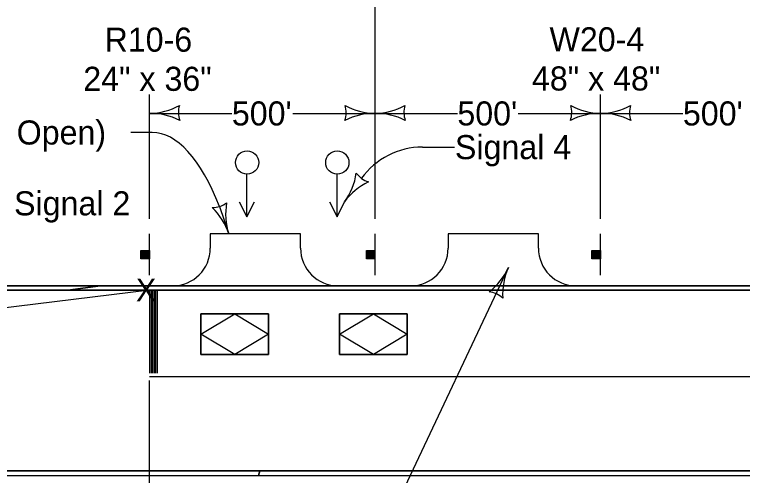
# Model space of a CAD drawing. Extents: x -2134934 to -2122394, y -2139046 to -2137036.
# Drawn here: x -2132604.2 to -2132120.1, y -2137668.2 to -2137362 of the extents above; entities that cross this region are included whole.
import ezdxf

# ---------------------------------------------------------------- set-up
doc = ezdxf.new("R2010")
doc.units = 0
for name, color, linetype in [('Barrier', 7, 'Continuous'), ('BridgeSuperStructureExisting', 7, 'Continuous'), ('DsnShtPlotIdentification', 7, 'Continuous'), ('DsnShtPlotShape', 7, 'Continuous'), ('dsnTextFinalPlan', 7, 'Continuous')]:
    doc.layers.add(name, color=color, linetype=linetype)

msp = doc.modelspace()

# ---------------------------------------------------------------- linework, layer by layer
at = {"layer": 'BridgeSuperStructureExisting'}
for p, q in [((-2132364.45, -2137497.66), (-2132364.45, -2137346.75)), ((-2132514.45, -2137497.66), (-2132514.45, -2137415.16)), ((-2132214.45, -2137497.66), (-2132214.45, -2137415.16)), ((-2132514.45, -2137427.66), (-2132459.7, -2137427.66)), ((-2132419.2, -2137427.66), (-2132364.45, -2137427.66)), ((-2132364.45, -2137427.66), (-2132309.7, -2137427.66)), ((-2132269.2, -2137427.66), (-2132214.45, -2137427.66)), ((-2132214.45, -2137427.66), (-2132159.7, -2137427.66)), ((-2132512.66, -2137440.32), (-2132526.88, -2137440.32)), ((-2132332.96, -2137450.05), (-2132311.59, -2137450.05)), ((-2132449.92, -2137468.02), (-2132449.92, -2137495.97)), ((-2132389.92, -2137468.02), (-2132389.92, -2137495.97)), ((-2132467.94, -2137489.45), (-2132461.8, -2137507.67)), ((-2132514.45, -2137535.16), (-2132514.45, -2137507.66)), ((-2132364.45, -2137535.16), (-2132364.45, -2137507.66)), ((-2132214.45, -2137535.16), (-2132214.45, -2137507.66)), ((-2132519.77, -2137524.3), (-2132519.77, -2137518.71)), ((-2132519.45, -2137518.71), (-2132519.45, -2137524.3)), ((-2132519.23, -2137524.3), (-2132519.23, -2137518.71)), ((-2132518.91, -2137518.71), (-2132518.91, -2137524.3)), ((-2132518.68, -2137524.3), (-2132518.7, -2137518.71)), ((-2132518.27, -2137518.71), (-2132518.25, -2137524.3)), ((-2132518.05, -2137524.3), (-2132518.05, -2137518.71)), ((-2132517.62, -2137518.71), (-2132517.62, -2137524.3)), ((-2132517.24, -2137524.3), (-2132517.24, -2137518.71)), ((-2132516.92, -2137518.71), (-2132516.9, -2137524.3)), ((-2132516.7, -2137524.3), (-2132516.7, -2137518.71)), ((-2132516.43, -2137518.71), (-2132516.43, -2137524.3)), ((-2132516.1, -2137524.3), (-2132516.1, -2137518.71)), ((-2132515.89, -2137518.71), (-2132515.89, -2137524.3)), ((-2132515.67, -2137524.3), (-2132515.67, -2137518.71)), ((-2132515.4, -2137518.71), (-2132515.4, -2137524.3)), ((-2132515.14, -2137524.3), (-2132515.14, -2137518.71)), ((-2132514.86, -2137518.71), (-2132514.86, -2137524.3)), ((-2132369.77, -2137524.3), (-2132369.77, -2137518.71)), ((-2132369.45, -2137518.71), (-2132369.45, -2137524.3)), ((-2132369.23, -2137524.3), (-2132369.23, -2137518.71)), ((-2132368.91, -2137518.71), (-2132368.91, -2137524.3)), ((-2132368.68, -2137524.3), (-2132368.7, -2137518.71)), ((-2132368.27, -2137518.71), (-2132368.25, -2137524.3)), ((-2132368.05, -2137524.3), (-2132368.05, -2137518.71)), ((-2132367.62, -2137518.71), (-2132367.62, -2137524.3)), ((-2132367.24, -2137524.3), (-2132367.24, -2137518.71)), ((-2132366.92, -2137518.71), (-2132366.9, -2137524.3)), ((-2132366.7, -2137524.3), (-2132366.7, -2137518.71)), ((-2132366.43, -2137518.71), (-2132366.43, -2137524.3)), ((-2132366.1, -2137524.3), (-2132366.1, -2137518.71)), ((-2132365.89, -2137518.71), (-2132365.89, -2137524.3)), ((-2132365.67, -2137524.3), (-2132365.67, -2137518.71)), ((-2132365.4, -2137518.71), (-2132365.4, -2137524.3)), ((-2132365.14, -2137524.3), (-2132365.14, -2137518.71)), ((-2132364.86, -2137518.71), (-2132364.86, -2137524.3)), ((-2132219.77, -2137524.3), (-2132219.77, -2137518.71)), ((-2132219.45, -2137518.71), (-2132219.45, -2137524.3)), ((-2132219.23, -2137524.3), (-2132219.23, -2137518.71)), ((-2132218.91, -2137518.71), (-2132218.91, -2137524.3)), ((-2132218.69, -2137524.3), (-2132218.7, -2137518.71)), ((-2132218.27, -2137518.71), (-2132218.25, -2137524.3)), ((-2132218.05, -2137524.3), (-2132218.05, -2137518.71)), ((-2132217.62, -2137518.71), (-2132217.62, -2137524.3)), ((-2132217.24, -2137524.3), (-2132217.24, -2137518.71)), ((-2132216.92, -2137518.71), (-2132216.9, -2137524.3)), ((-2132216.7, -2137524.3), (-2132216.7, -2137518.71)), ((-2132216.43, -2137518.71), (-2132216.43, -2137524.3)), ((-2132216.1, -2137524.3), (-2132216.1, -2137518.71)), ((-2132215.89, -2137518.71), (-2132215.89, -2137524.3)), ((-2132215.67, -2137524.3), (-2132215.67, -2137518.71)), ((-2132215.4, -2137518.71), (-2132215.4, -2137524.3)), ((-2132215.14, -2137524.3), (-2132215.14, -2137518.71)), ((-2132214.86, -2137518.71), (-2132214.86, -2137524.3)), ((-2132414.88, -2137824.64), (-2132275.76, -2137530.07)), ((-2132499.02, -2137542.16), (-2132389.02, -2137542.16)), ((-2132340.81, -2137542.16), (-2132230.81, -2137542.16)), ((-2131861.99, -2137545.16), (-2133174.44, -2137545.16)), ((-2132514.45, -2137545.16), (-2133004.39, -2137605.15)), ((-2132514.45, -2137545.16), (-2132514.45, -2137600.16)), ((-2132513.45, -2137545.16), (-2132513.45, -2137600.16)), ((-2132512.45, -2137545.16), (-2132512.45, -2137600.16)), ((-2132511.45, -2137545.16), (-2132511.45, -2137600.16)), ((-2132510.45, -2137545.16), (-2132510.45, -2137600.16)), ((-2132509.45, -2137545.16), (-2132509.45, -2137600.16)), ((-2132480.28, -2137587.78), (-2132480.28, -2137560.78)), ((-2132480.28, -2137560.78), (-2132435.28, -2137560.78)), ((-2132480.28, -2137587.78), (-2132480.28, -2137560.78)), ((-2132480.28, -2137560.78), (-2132435.28, -2137560.78)), ((-2132435.28, -2137560.78), (-2132480.28, -2137560.78)), ((-2132480.28, -2137560.78), (-2132480.28, -2137587.78)), ((-2132435.28, -2137587.78), (-2132435.28, -2137560.78)), ((-2132435.28, -2137560.78), (-2132435.28, -2137587.78)), ((-2132435.28, -2137587.78), (-2132435.28, -2137560.78)), ((-2132388.09, -2137587.86), (-2132388.09, -2137560.86)), ((-2132388.09, -2137560.86), (-2132343.09, -2137560.86)), ((-2132388.09, -2137587.86), (-2132388.09, -2137560.86)), ((-2132388.09, -2137560.86), (-2132343.09, -2137560.86)), ((-2132343.09, -2137560.86), (-2132388.09, -2137560.86)), ((-2132388.09, -2137560.86), (-2132388.09, -2137587.86)), ((-2132343.09, -2137587.86), (-2132343.09, -2137560.86)), ((-2132343.09, -2137560.86), (-2132343.09, -2137587.86)), ((-2132343.09, -2137587.86), (-2132343.09, -2137560.86)), ((-2132480.28, -2137587.78), (-2132435.28, -2137587.78)), ((-2132435.28, -2137587.78), (-2132480.28, -2137587.78)), ((-2132480.28, -2137587.78), (-2132435.28, -2137587.78)), ((-2132388.09, -2137587.86), (-2132343.09, -2137587.86)), ((-2132343.09, -2137587.86), (-2132388.09, -2137587.86)), ((-2132388.09, -2137587.86), (-2132343.09, -2137587.86)), ((-2132514.45, -2137842.77), (-2132514.45, -2137605.16)), ((-2133364.44, -2137665.16), (-2131861.99, -2137665.16))]:
    msp.add_line(p, q, dxfattribs=at)
for points in [[(-2132454.74, -2137486.34), (-2132449.74, -2137496.34), (-2132444.74, -2137486.34)], [(-2132394.74, -2137486.34), (-2132389.74, -2137496.34), (-2132384.74, -2137486.34)], [(-2132414.02, -2137517.16), (-2132414.02, -2137507.67), (-2132474.02, -2137507.67), (-2132474.02, -2137517.16)], [(-2132255.81, -2137517.16), (-2132255.81, -2137507.67), (-2132315.81, -2137507.67), (-2132315.81, -2137517.16)]]:
    msp.add_lwpolyline(points, dxfattribs=at)
for points in [[(-2132514.54, -2137518.71), (-2132514.54, -2137524.34), (-2132520.17, -2137524.34), (-2132520.17, -2137518.71)], [(-2132364.54, -2137518.71), (-2132364.54, -2137524.34), (-2132370.17, -2137524.34), (-2132370.17, -2137518.71)], [(-2132214.54, -2137518.71), (-2132214.54, -2137524.34), (-2132220.17, -2137524.34), (-2132220.17, -2137518.71)]]:
    msp.add_lwpolyline(points, close=True, dxfattribs=at)
for centre in [(-2132449.56, -2137460.29), (-2132389.56, -2137460.29)]:
    msp.add_circle(centre, 7.74, dxfattribs=at)
for centre, radius, start, end in [((-2132515.2, -2137385.17), 42.5, 271.0176, 299.0725), ((-2132478.83, -2137427.04), 16.42, 163.2666, 198.7334), ((-2132400.06, -2137427.04), 16.42, 341.2666, 16.7334), ((-2132363.69, -2137385.17), 42.5, 240.9275, 268.9824), ((-2132365.2, -2137385.17), 42.5, 271.0176, 299.0725), ((-2132328.83, -2137427.04), 16.42, 163.2666, 198.7334), ((-2132250.06, -2137427.04), 16.42, 341.2666, 16.7334), ((-2132213.69, -2137385.17), 42.5, 240.9275, 268.9824), ((-2132215.2, -2137385.17), 42.5, 271.0176, 299.0725), ((-2132178.83, -2137427.04), 16.42, 163.2666, 198.7334), ((-2132513.72, -2137470.15), 42.5, 62.9275, 90.9824), ((-2132365.17, -2137470.15), 42.5, 89.0176, 117.0725), ((-2132363.72, -2137470.15), 42.5, 62.9275, 90.9824), ((-2132215.17, -2137470.15), 42.5, 89.0176, 117.0725), ((-2132213.72, -2137470.15), 42.5, 62.9275, 90.9824), ((-2132332.96, -2137500.05), 50, 90, 144.138), ((-2132499.02, -2137517.16), 25, 270, 0), ((-2132389.02, -2137517.16), 25, 180, 270), ((-2132340.81, -2137517.16), 25, 270, 0), ((-2132230.81, -2137517.16), 25, 180, 270)]:
    msp.add_arc(centre, radius, start, end, dxfattribs=at)
msp.add_ellipse((-2132512.66, -2137653.25), major_axis=(0, 212.93), ratio=0.328743, start_param=5.590023, end_param=6.283185, dxfattribs=at)
at = {"layer": 'DsnShtPlotIdentification'}
for p, q in [((-2132547.01, -2137542.16), (-2132860.67, -2137542.16)), ((-2132547.01, -2137542.16), (-2132568.69, -2137545.16)), ((-2132568.69, -2137545.16), (-2132547.01, -2137542.16)), ((-2131861.99, -2137542.16), (-2132547.01, -2137542.16)), ((-2132861.64, -2137545.16), (-2132568.69, -2137545.16)), ((-2132568.69, -2137545.16), (-2132514.45, -2137545.16)), ((-2132509.45, -2137545.16), (-2131861.99, -2137545.16)), ((-2131861.95, -2137602.66), (-2132514.45, -2137602.66)), ((-2133364.44, -2137665.16), (-2131861.99, -2137665.16)), ((-2133364.44, -2137665.16), (-2131861.99, -2137665.16)), ((-2133364.44, -2137668.16), (-2131861.99, -2137668.16)), ((-2132441.05, -2137665.16), (-2132714.94, -2137665.16)), ((-2132714.94, -2137668.16), (-2132442.06, -2137668.16)), ((-2132442.06, -2137668.16), (-2132441.05, -2137665.16)), ((-2132441.05, -2137665.16), (-2132442.06, -2137668.16)), ((-2132442.06, -2137668.16), (-2131861.99, -2137668.16)), ((-2131861.99, -2137665.16), (-2132441.05, -2137665.16))]:
    msp.add_line(p, q, dxfattribs=at)
for points in [[(-2133174.44, -2137542.16), (-2131861.99, -2137542.16)], [(-2133174.44, -2137545.16), (-2131861.99, -2137545.16)], [(-2133173.75, -2137545.16), (-2131861.29, -2137545.16)], [(-2132514.45, -2137545.16), (-2132513.45, -2137545.16), (-2132512.45, -2137545.16)], [(-2132512.45, -2137545.16), (-2132511.45, -2137545.16), (-2132510.45, -2137545.16), (-2132509.45, -2137545.16)]]:
    msp.add_lwpolyline(points, dxfattribs=at)
at = {"layer": 'DsnShtPlotShape'}
for centre, radius, start, end in [((-2132418.99, -2137461.18), 42.5, 323.701, 351.7735), ((-2132363.64, -2137457.62), 16.42, 215.9676, 251.4343), ((-2132350.49, -2137511.5), 42.5, 115.6285, 143.701), ((-2132472.76, -2137473.76), 16.42, 270.1817, 305.6484), ((-2132421.36, -2137494.6), 42.5, 169.8426, 197.9151), ((-2132502.24, -2137520.74), 42.5, 17.9151, 45.9876), ((-2132314.41, -2137512.39), 42.5, 307.3534, 335.4259), ((-2132237.11, -2137547.74), 42.5, 155.4259, 183.4984), ((-2132290.58, -2137562.47), 16.42, 47.6925, 83.1592)]:
    msp.add_arc(centre, radius, start, end, dxfattribs=at)
at = {"layer": 'dsnTextFinalPlan'}
for points in [[(-2132480.28, -2137574.28), (-2132457.78, -2137560.78), (-2132435.28, -2137574.28), (-2132457.78, -2137587.78)], [(-2132388.09, -2137574.36), (-2132365.59, -2137560.86), (-2132343.09, -2137574.36), (-2132365.59, -2137587.86)]]:
    msp.add_lwpolyline(points, close=True, dxfattribs=at)

# ---------------------------------------------------------------- texts
at = {"layer": 'Barrier'}
for s, p in [('R10-6', (-2132544.37, -2137386.66)), ('W20-4', (-2132248.4, -2137386.44)), ('24" x 36"', (-2132558.51, -2137412.66)), ('48" x 48"', (-2132260.1, -2137412.44))]:
    msp.add_text(s, height=16, dxfattribs=at).set_placement(p)
at = {"layer": 'BridgeSuperStructureExisting'}
for s, height, p in [("500'", 16, (-2132459.7, -2137435.66)), ("500'", 16, (-2132309.7, -2137435.66)), ("500'", 16, (-2132159.7, -2137435.66)), ('NB I-35 Entrance Ramp (To Remain Open)', 16, (-2132953.6, -2137448.32)), ('Signal 4', 16, (-2132311.32, -2137458.05)), ('Signal 2', 16, (-2132604.56, -2137495.39)), ('X', 15, (-2132523.45, -2137552.51))]:
    msp.add_text(s, height=height, dxfattribs=at).set_placement(p)

doc.saveas('drawing.dxf')
